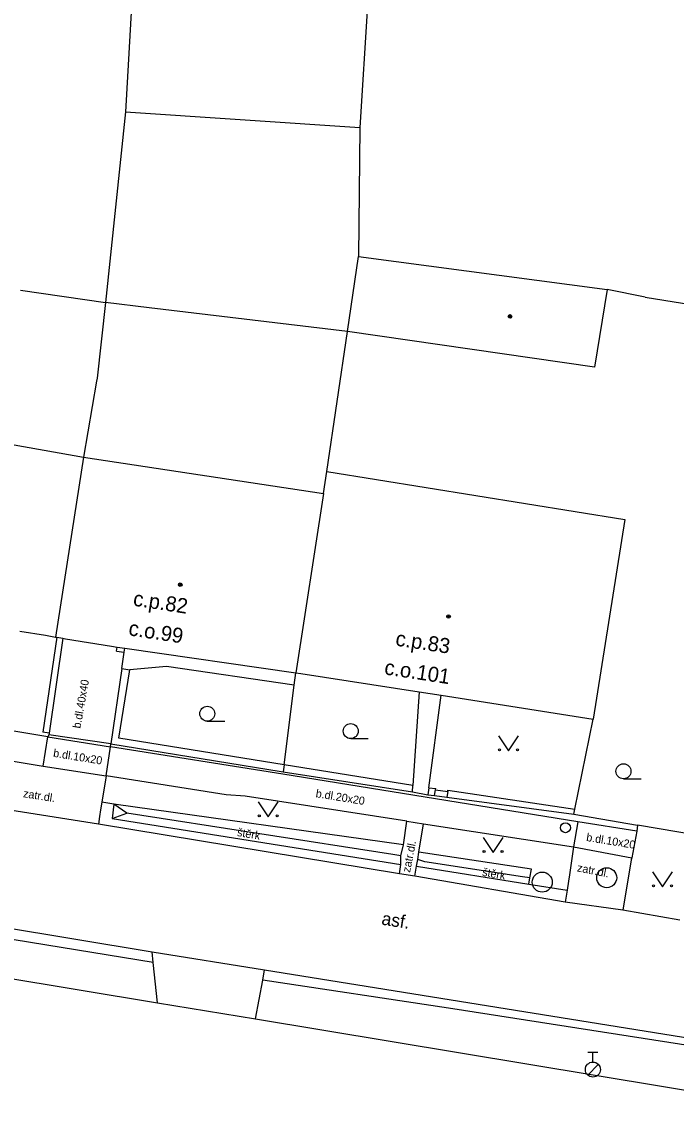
# Model space of a CAD drawing. Extents: x -591353 to -591106, y -1167325 to -1167155.
# Drawn here: x -591327.7 to -591295, y -1167266.9 to -1167212.5 of the extents above; entities that cross this region are included whole.
import ezdxf

# ---------------------------------------------------------------- set-up
doc = ezdxf.new("R2010")
doc.units = 0
for name, color, linetype in [('Level 24', 7, 'Continuous'), ('Level 27', 7, 'Continuous'), ('Level 28', 7, 'Continuous'), ('Level 31', 7, 'Continuous'), ('Level 36', 7, 'Continuous'), ('Level 39', 7, 'Continuous'), ('Vrstva 10', 7, 'Continuous'), ('Vrstva 11', 7, 'Continuous'), ('Vrstva 40', 7, 'Continuous'), ('Vrstva 46', 7, 'Continuous'), ('Vrstva 5', 7, 'Continuous'), ('Vrstva 51', 7, 'Continuous'), ('Vrstva 6', 7, 'Continuous'), ('Vrstva 7', 7, 'Continuous'), ('Vrstva 8', 7, 'Continuous')]:
    doc.layers.add(name, color=color, linetype=linetype)

msp = doc.modelspace()

# ---------------------------------------------------------------- linework, layer by layer
at = {"layer": 'Level 24'}
for points in [[(-591323.02, -1167243.99), (-591322.98, -1167243.78)], [(-591323.02, -1167243.99), (-591322.628, -1167244.031)], [(-591322.628, -1167244.031), (-591322.6, -1167243.84)], [(-591307.45, -1167251.16), (-591307.12, -1167251.2)], [(-591307.12, -1167251.2), (-591307.07, -1167250.91)], [(-591307.12, -1167251.2), (-591306.51, -1167251.28)], [(-591307.07, -1167250.91), (-591306.46, -1167251)], [(-591306.46, -1167251), (-591306.51, -1167251.28)]]:
    msp.add_lwpolyline(points, dxfattribs=at)
at = {"layer": 'Level 27'}
for centre in [(-591301.74, -1167255.53), (-591298.52, -1167255.31)]:
    msp.add_circle(centre, 0.5, dxfattribs=at)
at = {"layer": 'Level 28'}
for p, q in [((-591299.46, -1167264.025), (-591298.96, -1167264.025)), ((-591299.21, -1167264.525), (-591299.21, -1167264.025)), ((-591299.468, -1167265.172), (-591298.938, -1167264.642))]:
    msp.add_line(p, q, dxfattribs=at)
msp.add_circle((-591299.21, -1167264.9), 0.375, dxfattribs=at)
at = {"layer": 'Level 31'}
msp.add_circle((-591300.58, -1167252.81), 0.25, dxfattribs=at)
at = {"layer": 'Level 36'}
for p, q in [((-591318.48, -1167247.485), (-591317.605, -1167247.485)), ((-591311.31, -1167248.355), (-591310.435, -1167248.355)), ((-591297.68, -1167250.365), (-591296.805, -1167250.365))]:
    msp.add_line(p, q, dxfattribs=at)
for points in [[(-591303.92, -1167248.22), (-591303.42, -1167248.97), (-591302.92, -1167248.22)], [(-591315.93, -1167251.52), (-591315.43, -1167252.27), (-591314.93, -1167251.52)], [(-591304.7, -1167253.3), (-591304.2, -1167254.05), (-591303.7, -1167253.3)], [(-591296.23, -1167255.02), (-591295.73, -1167255.77), (-591295.23, -1167255.02)]]:
    msp.add_lwpolyline(points, dxfattribs=at)
for centre, radius in [((-591318.48, -1167247.11), 0.375), ((-591311.31, -1167247.98), 0.375), ((-591303.87, -1167248.92), 0.05), ((-591302.971, -1167248.92), 0.05), ((-591297.68, -1167249.99), 0.375), ((-591315.88, -1167252.22), 0.05), ((-591314.981, -1167252.22), 0.05), ((-591304.65, -1167254), 0.05), ((-591303.751, -1167254), 0.05), ((-591296.18, -1167255.72), 0.05), ((-591295.281, -1167255.72), 0.05)]:
    msp.add_circle(centre, radius, dxfattribs=at)
at = {"layer": 'Level 39'}
for centre, radius in [((-591303.35, -1167227.25), 0.09), ((-591303.35, -1167227.25), 0.0398), ((-591319.83, -1167240.66), 0.09), ((-591319.83, -1167240.66), 0.0398), ((-591306.42, -1167242.25), 0.09), ((-591306.42, -1167242.25), 0.0398)]:
    msp.add_circle(centre, radius, dxfattribs=at)
at = {"layer": 'Vrstva 10'}
msp.add_line((-591352.572, -1167253.793), (-591321.23, -1167259.02), dxfattribs=at)
for points in [[(-591323.92, -1167252.63), (-591328.67, -1167251.89)], [(-591308.88, -1167255.12), (-591323.92, -1167252.63)], [(-591308.1, -1167255.24), (-591308.88, -1167255.12)], [(-591300.59, -1167256.53), (-591308.1, -1167255.24)], [(-591297.72, -1167256.94), (-591300.59, -1167256.53)], [(-591294.86, -1167257.43), (-591297.72, -1167256.94)], [(-591321.23, -1167259.02), (-591315.62, -1167259.92)], [(-591315.62, -1167259.92), (-591254.87, -1167269.68), (-591254.39, -1167269.76), (-591239.02, -1167272.22)]]:
    msp.add_lwpolyline(points, dxfattribs=at)
at = {"layer": 'Vrstva 11'}
for points in [[(-591322.75, -1167244.85), (-591322.628, -1167244.031)], [(-591314.14, -1167245.69), (-591320.52, -1167244.75), (-591322.35, -1167244.92)], [(-591307.89, -1167246.02), (-591308.21, -1167250.7)], [(-591307.4, -1167250.82), (-591306.79, -1167246.19)], [(-591326.45, -1167248.27), (-591330.64, -1167247.57)], [(-591326.68, -1167249.73), (-591326.45, -1167248.27)], [(-591326.4, -1167248.16), (-591326.45, -1167248.27)], [(-591326.45, -1167248.27), (-591323.31, -1167248.76)], [(-591326.38, -1167248.08), (-591326.4, -1167248.16)], [(-591323.3, -1167248.62), (-591326.4, -1167248.16)], [(-591323.54, -1167250.22), (-591323.31, -1167248.76)], [(-591323.31, -1167248.76), (-591323.3, -1167248.62)], [(-591314.7, -1167250.14), (-591323.31, -1167248.76)], [(-591328.28, -1167249.46), (-591326.68, -1167249.73)], [(-591326.68, -1167249.73), (-591323.54, -1167250.22)], [(-591314.79, -1167250), (-591314.68, -1167250.02)], [(-591299.96, -1167252.52), (-591314.7, -1167250.14)], [(-591323.54, -1167250.22), (-591323.75, -1167251.54)], [(-591308.5, -1167252.48), (-591316.58, -1167251.23), (-591317.53, -1167251.17), (-591323.54, -1167250.22)], [(-591323.75, -1167251.54), (-591323.81, -1167251.91)], [(-591323.15, -1167251.63), (-591323.75, -1167251.54)], [(-591323.15, -1167251.63), (-591323.24, -1167252.35)], [(-591322.5, -1167252.09), (-591323.15, -1167251.63)], [(-591308.67, -1167253.67), (-591323.15, -1167251.63)], [(-591323.86, -1167252.25), (-591323.92, -1167252.63)], [(-591323.81, -1167251.91), (-591323.86, -1167252.25)], [(-591323.24, -1167252.35), (-591322.5, -1167252.09)], [(-591323.24, -1167252.35), (-591308.8, -1167254.65)], [(-591308.8, -1167254.22), (-591309.2, -1167254.15), (-591322.5, -1167252.09)], [(-591308.67, -1167253.67), (-591308.5, -1167252.48)], [(-591308.5, -1167252.48), (-591307.68, -1167252.61)], [(-591307.9, -1167254.04), (-591307.68, -1167252.61)], [(-591307.68, -1167252.61), (-591300.17, -1167253.77)], [(-591299.96, -1167252.52), (-591300.17, -1167253.77)], [(-591297.02, -1167252.99), (-591299.96, -1167252.52)], [(-591296.98, -1167252.69), (-591297.02, -1167252.99)], [(-591297.02, -1167252.99), (-591297.27, -1167254.32)], [(-591308.8, -1167254.22), (-591308.67, -1167253.67)], [(-591300.17, -1167253.77), (-591300.38, -1167255.17)], [(-591300.17, -1167253.77), (-591297.27, -1167254.32)], [(-591321.18, -1167259.55), (-591332.74, -1167257.67), (-591349.84, -1167254.71), (-591352.572, -1167254.294)], [(-591308.8, -1167254.65), (-591308.8, -1167254.22)], [(-591308.02, -1167254.74), (-591307.96, -1167254.4)], [(-591307.96, -1167254.4), (-591307.9, -1167254.04)], [(-591302.36, -1167255.32), (-591302.72, -1167255.26), (-591307.6, -1167254.52), (-591307.96, -1167254.4)], [(-591302.28, -1167254.88), (-591307.9, -1167254.04)], [(-591297.29, -1167254.42), (-591297.72, -1167256.94)], [(-591297.27, -1167254.32), (-591297.29, -1167254.42)], [(-591308.88, -1167255.12), (-591308.8, -1167254.65)], [(-591308.1, -1167255.24), (-591308.02, -1167254.74)], [(-591308.02, -1167254.74), (-591302.41, -1167255.64)], [(-591302.36, -1167255.32), (-591302.28, -1167254.88)], [(-591302.41, -1167255.64), (-591302.36, -1167255.32)], [(-591302.41, -1167255.64), (-591300.5, -1167255.94)], [(-591300.43, -1167255.48), (-591300.5, -1167255.94)], [(-591300.38, -1167255.17), (-591300.43, -1167255.48)], [(-591300.5, -1167255.94), (-591300.59, -1167256.53)], [(-591352.572, -1167256.425), (-591348.99, -1167256.91), (-591320.97, -1167261.56)], [(-591321.18, -1167259.55), (-591321.23, -1167259.02)], [(-591320.97, -1167261.56), (-591321.18, -1167259.55)], [(-591315.71, -1167260.43), (-591315.62, -1167259.92)], [(-591316.07, -1167262.37), (-591315.71, -1167260.43)], [(-591239.14, -1167272.71), (-591240.68, -1167272.27), (-591248.29, -1167271.11), (-591264.99, -1167268.44), (-591281.22, -1167265.9), (-591290.29, -1167264.35), (-591306.42, -1167261.83), (-591315.71, -1167260.43)], [(-591320.97, -1167261.56), (-591316.07, -1167262.37)], [(-591316.07, -1167262.37), (-591254.81, -1167272.53), (-591239.7, -1167275.04)]]:
    msp.add_lwpolyline(points, dxfattribs=at)
at = {"layer": 'Vrstva 5'}
for points in [[(-591311.47, -1167228.01), (-591310.92, -1167224.26)], [(-591310.92, -1167224.26), (-591298.5, -1167225.9)], [(-591298.5, -1167225.9), (-591299.13, -1167229.78)], [(-591299.13, -1167229.78), (-591311.47, -1167228.01)], [(-591328.9, -1167233.54), (-591324.66, -1167234.28)], [(-591324.66, -1167234.28), (-591326.07, -1167243.28)], [(-591324.66, -1167234.28), (-591312.67, -1167236.1)], [(-591312.67, -1167236.1), (-591312.5, -1167235.01)], [(-591312.5, -1167235.01), (-591297.62, -1167237.41)], [(-591312.67, -1167236.1), (-591314.06, -1167245.06)], [(-591297.62, -1167237.41), (-591299.19, -1167247.38)], [(-591326.57, -1167243.19), (-591326.07, -1167243.28)], [(-591326.07, -1167243.28), (-591325.99, -1167243.29)], [(-591325.99, -1167243.29), (-591325.69, -1167243.34)], [(-591325.69, -1167243.34), (-591325.56, -1167243.36)], [(-591323.27, -1167243.73), (-591322.98, -1167243.78)], [(-591322.98, -1167243.78), (-591322.6, -1167243.84)], [(-591322.6, -1167243.84), (-591314.06, -1167245.06)], [(-591314.06, -1167245.06), (-591313.81, -1167245.1)], [(-591313.81, -1167245.1), (-591307.89, -1167246.02)], [(-591307.89, -1167246.02), (-591306.79, -1167246.19)], [(-591306.79, -1167246.19), (-591299.19, -1167247.38)]]:
    msp.add_lwpolyline(points, dxfattribs=at)
at = {"layer": 'Vrstva 51'}
for points in [[(-591322.1, -1167208.81), (-591322.56, -1167217.02)], [(-591310.48, -1167211.7), (-591310.85, -1167217.8)], [(-591322.56, -1167217.02), (-591323.56, -1167226.55)], [(-591322.56, -1167217.02), (-591310.85, -1167217.8)], [(-591310.85, -1167217.8), (-591310.92, -1167224.26)], [(-591327.82, -1167225.94), (-591323.56, -1167226.55)], [(-591296.6, -1167226.29), (-591298.5, -1167225.9)], [(-591323.56, -1167226.55), (-591323.99, -1167230.33)], [(-591321.38, -1167226.82), (-591323.56, -1167226.55)], [(-591296.6, -1167226.29), (-591291.94, -1167227.04)], [(-591311.47, -1167228.01), (-591321.38, -1167226.82)], [(-591312.5, -1167235.01), (-591311.47, -1167228.01)], [(-591324.02, -1167230.49), (-591324.66, -1167234.28)], [(-591323.99, -1167230.33), (-591324.02, -1167230.49)]]:
    msp.add_lwpolyline(points, dxfattribs=at)
at = {"layer": 'Vrstva 6'}
for points in [[(-591327.84, -1167242.98), (-591326.57, -1167243.19)], [(-591325.56, -1167243.36), (-591323.27, -1167243.73)]]:
    msp.add_lwpolyline(points, dxfattribs=at)
at = {"layer": 'Vrstva 7'}
for points in [[(-591325.99, -1167243.29), (-591326.7, -1167248.03)], [(-591325.69, -1167243.34), (-591326.38, -1167248.08)], [(-591322.75, -1167244.85), (-591323.3, -1167248.62)], [(-591314.64, -1167249.67), (-591322.9, -1167248.34), (-591322.35, -1167244.92)], [(-591322.75, -1167244.85), (-591322.35, -1167244.92)], [(-591314.14, -1167245.69), (-591314.06, -1167245.06)], [(-591314.64, -1167249.67), (-591314.14, -1167245.69)], [(-591300.11, -1167251.89), (-591299.19, -1167247.38)], [(-591326.38, -1167248.08), (-591326.7, -1167248.03)], [(-591323.3, -1167248.62), (-591314.79, -1167250)], [(-591314.64, -1167249.67), (-591314.68, -1167250.02)], [(-591308.21, -1167250.7), (-591314.64, -1167249.67)], [(-591314.68, -1167250.02), (-591308.23, -1167251.02)], [(-591308.23, -1167251.02), (-591308.21, -1167250.7)], [(-591307.4, -1167250.82), (-591307.45, -1167251.16)], [(-591307.4, -1167250.82), (-591307.06, -1167250.85)], [(-591307.07, -1167250.91), (-591307.06, -1167250.85)], [(-591306.51, -1167251.28), (-591300.16, -1167252.14)], [(-591306.46, -1167251), (-591306.45, -1167250.93)], [(-591306.45, -1167250.93), (-591300.11, -1167251.89)], [(-591300.16, -1167252.14), (-591300.11, -1167251.89)], [(-591282.18, -1167255.04), (-591293.93, -1167253.2), (-591296.98, -1167252.69)]]:
    msp.add_lwpolyline(points, dxfattribs=at)
at = {"layer": 'Vrstva 8'}
for points in [[(-591308.23, -1167251.02), (-591307.45, -1167251.16)], [(-591300.16, -1167252.14), (-591296.98, -1167252.69)]]:
    msp.add_lwpolyline(points, dxfattribs=at)

# ---------------------------------------------------------------- texts
at = {"layer": 'Vrstva 40'}
for s, height, rotation, p in [('b.dl.40x40', 0.4, 79.8687, (-591324.82, -1167247.87)), ('b.dl.10x20', 0.4, 350.7751, (-591326.2, -1167249.26)), ('zatr.dl.', 0.4, 351, (-591327.7, -1167251.28)), ('b.dl.20x20', 0.4, 350.7751, (-591313.08, -1167251.28)), ('štěrk', 0.4, 350.4518, (-591317.01, -1167253.22)), ('b.dl.10x20', 0.4, 350.7751, (-591299.56, -1167253.47)), ('zatr.dl.', 0.4, 78.7761, (-591308.35, -1167255.07)), ('štěrk', 0.4, 350.4518, (-591304.76, -1167255.21)), ('zatr.dl.', 0.4, 349, (-591300.02, -1167254.99)), ('asf.', 0.65, 350.9583, (-591309.8, -1167257.65))]:
    msp.add_text(s, height=height, rotation=rotation, dxfattribs=at).set_placement(p)
at = {"layer": 'Vrstva 46'}
for s, rotation, p in [('c.p.82', 351.28, (-591322.217, -1167241.703)), ('c.o.99', 351.28, (-591322.446, -1167243.184)), ('c.p.83', 351.3383, (-591309.106, -1167243.701)), ('c.o.101', 351.3383, (-591309.661, -1167245.14))]:
    msp.add_text(s, height=0.75, rotation=rotation, dxfattribs=at).set_placement(p)

doc.saveas('drawing.dxf')
